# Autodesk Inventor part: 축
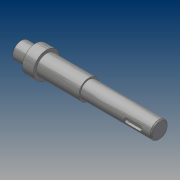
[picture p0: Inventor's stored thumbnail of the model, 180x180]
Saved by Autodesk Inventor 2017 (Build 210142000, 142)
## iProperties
Created: 2015-09
Part Number: 축
Material: 강철, 연강
Document SubType Name: Modeling
Designer: mduedu
Density: 7.86 g/cm^3
Mass: 263.424 g
Surface Area: 86.4309 cm^2
Volume: 33.5145 cm^3
Appearance: 강철
Author: mduedu
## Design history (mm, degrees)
sketch "스케치1"
  geometry: L1 (-69, 0)-(69, 0); L2 (-69, 0)-(-69, 8.5); L3 (-69, 8.5)-(-54, 8.5); L4 (-54, 8.5)-(-54, 13); L5 (-54, 13)-(-43, 13); L6 (-43, 13)-(-43, 10); L7 (-43, 10)-(-1, 10); L8 (-1, 10)-(-1, 8.5); L9 (-1, 8.5)-(69, 8.5); L10 (69, 8.5)-(69, 0); 2 further points
  constraints: 20 end point, 5 parallel, 2 horizontal, 2 perpendicular, 1 coincident, 1 midpoint, 1 vertical
  dimensions: "d0" = 138 distance of L1.start L1.end; "d2" = 11 distance of L4.end L5.end; "d3" = 42 distance of L6.end L7.end; "d4" = 70 distance of L8.end L9.end; "d5" = 17 diameter of L3 L1; "d6" = 17 diameter of L9 L1; "d7" = 20 diameter of L7 L1; "d8" = 26 diameter of L5 L1
revolve "회전1" sketch "스케치1" stored, may be unused: angle "d9" = 90 deg
node "작업 평면1"
sketch "스케치2"
  geometry: L1 (10.5, 2.5)-(23.5, 2.5); L2 (23.5, -2.5)-(10.5, -2.5); L3 (10.5, 2.5)-(23.5, -2.5); L4 (23.5, 2.5)-(10.5, -2.5); L5 (35, -8.5)-(35, 8.5) reference; A1 r 2.5 centre (10.5, 0) between (10.5, 2.5) and (10.5, -2.5); A2 r 2.5 centre (23.5, 0) between (23.5, -2.5) and (23.5, 2.5); 2 further points
  constraints: 8 end point, 4 point on circle, 4 tangent, 2 centre point, 2 midpoint, 1 horizontal, 1 horizontal alignment, 1 parallel
  dimensions: "d10" = 18 dimension on A2 A1; "d12" = 9 distance edge to line of A2 L5; "d13" = 5 distance between parallel lines of L2 L1
extrude "돌출1" cut sketch "스케치2" distance "d14" = 3; taper "d15" = 0 deg
node "작업 평면2"
sketch "스케치4"
  geometry: L1 (7, -3)-(-9, -3); L2 (-9, 3)-(7, 3); L3 (-21, 10)-(-21, -10) reference; A1 r 3 centre (-9, 0) between (-9, 3) and (-9, -3); A2 r 3 centre (7, 0) between (7, -3) and (7, 3); 1 further point
  constraints: 4 end point, 4 point on circle, 4 tangent, 2 centre point, 1 horizontal, 1 horizontal alignment, 1 parallel
  dimensions: "d16" = 22 dimension on A1 A2; "d18" = 6 distance between parallel lines of L2 L1; "d19" = 9 distance edge to line of A1 L3
extrude "돌출2" cut sketch "스케치4" distance "d20" = 3.5; taper "d21" = 0 deg
sketch "스케치5"
  geometry: L1 (-1, 8.5)-(69, 8.5) reference; L2 (-1, -8.5)-(69, -8.5) reference; L3 (42, 8.5)-(42, -8.5); L4 (42, -6.5)-(40, -8.5); L5 (42, -8.5)-(40, -8.5); L6 (42, -8.5)-(42, -6.5); L7 (-1, -10)-(-1, 10) reference; 1 further point
  constraints: 8 end point, 4 point on line, 1 collinear, 1 perpendicular
  dimensions: "d22" = 4 diameter of L4.end L3; "d24" = 45 deg angle of L3 L4; "d26" = 43 distance between parallel lines of L3 L7
revolve "회전2" sketch "스케치5" stored, may be unused: angle "d27" = 90 deg
chamfer "모따기1" distance "d28" = 1; stored, may be unused: second distance "d29" = 2, angle "d30" = 45 deg
sketch "스케치6"
  geometry: L1 (42, -6.5)-(40, -8.5) reference; L2 (42, -6.5)-(44, -8.5) reference; 2 further points
  constraints: 1 coincident
node "솔리드1"
